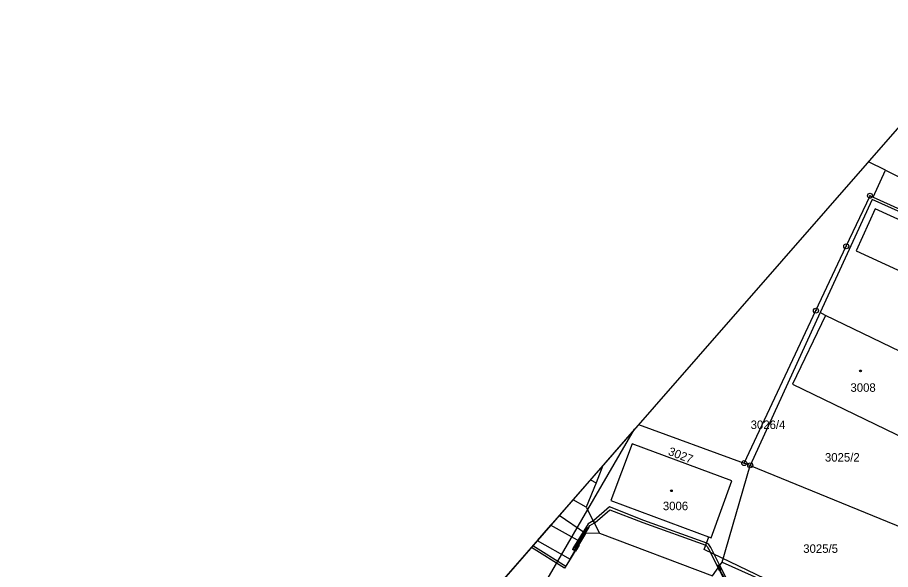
# Model space of a CAD drawing. Extents: x -620475 to -619963, y -1123010 to -1122510.
# Drawn here: x -620474.6 to -620299.9, y -1122620.5 to -1122510.1 of the extents above; entities that cross this region are included whole.
import ezdxf

# ---------------------------------------------------------------- set-up
doc = ezdxf.new("R2010")
doc.units = 0
for name, color, linetype in [('EON-podzemní NN', 7, 'Continuous'), ('HranDP', 7, 'Continuous'), ('Hranice parcel', 7, 'Continuous'), ('Parcelní čísla', 7, 'Continuous'), ('Rámečky', 7, 'Continuous'), ('Rámečky-tisk', 7, 'Continuous'), ('VAS vodovod', 7, 'Continuous'), ('Vnitřní kresba', 7, 'Continuous'), ('Vrstva 17', 7, 'Continuous'), ('Vrstva 9', 7, 'Continuous'), ('Věcná břemena k části', 7, 'Continuous'), ('Značky bodu BP', 7, 'Continuous'), ('Značky budov', 7, 'Continuous')]:
    doc.layers.add(name, color=color, linetype=linetype)

# ---------------------------------------------------------------- blocks, each defined once
blk = doc.blocks.new('NN630')
at = {"layer": 'Vrstva 9'}
for points in [[(0, -0.7), (-0.7, 0)], [(-0.7, -0.7), (-0.7, 0), (0.7, 0), (0.7, -0.7)], [(-0.7, -0.7), (0.7, -0.7)], [(0, -0.7), (0.7, 0)]]:
    blk.add_lwpolyline(points, dxfattribs=at)

msp = doc.modelspace()

# ---------------------------------------------------------------- linework, layer by layer
at = {"layer": 'EON-podzemní NN'}
msp.add_lwpolyline([(-620360.3, -1122612.01), (-620362.69, -1122615.91), (-620362.46, -1122616.07), (-620362.68, -1122616.4), (-620363.23, -1122616.02), (-620360.88, -1122612.19)], close=True, dxfattribs=at)
for points in [[(-620360.59, -1122612.1), (-620362.96, -1122615.97), (-620362.57, -1122616.24)], [(-620334.14, -1122620.77), (-620334.63, -1122619.57), (-620334.27, -1122619.68), (-620334.11, -1122619.78), (-620333.78, -1122620.6)], [(-620300.69, -1122640.97), (-620301.3, -1122641.21), (-620302.14, -1122640.6), (-620304.66, -1122639.27), (-620309.25, -1122636.6), (-620312.29, -1122634.86), (-620318.07, -1122631.51), (-620322.97, -1122628.77), (-620331.18, -1122624.09), (-620332.6, -1122623.11), (-620333.96, -1122620.69), (-620334.38, -1122619.64)]]:
    msp.add_lwpolyline(points, dxfattribs=at)
at = {"layer": 'HranDP'}
msp.add_line((-620358.11, -1122613.18), (-620335.54, -1122621.75), dxfattribs=at)
msp.add_lwpolyline([(-620358.11, -1122613.18), (-620360.91, -1122613.28), (-620361.94, -1122614.97), (-620364.03, -1122618.38), (-620365.14, -1122620.19), (-620371.77, -1122616.05)], dxfattribs=at)
at = {"layer": 'Hranice parcel'}
for p, q in [((-620300.93, -1122540.63), (-620304.33, -1122538.95)), ((-620303.36, -1122546.01), (-620300.93, -1122540.63)), ((-620303.56, -1122546.46), (-620313.95, -1122569.11)), ((-620269.23, -1122562), (-620303.56, -1122546.46)), ((-620303.36, -1122546.01), (-620269.35, -1122561.48)), ((-620313.95, -1122569.11), (-620327.97, -1122599.65)), ((-620312.88, -1122569.65), (-620313.95, -1122569.11)), ((-620350.31, -1122591.51), (-620329.18, -1122599.21)), ((-620357.46, -1122599.69), (-620358.78, -1122603.15)), ((-620333.59, -1122619.01), (-620327.97, -1122599.65)), ((-620327.97, -1122599.65), (-620329.18, -1122599.21)), ((-620327.97, -1122599.65), (-620295.2, -1122613.12)), ((-620358.78, -1122603.15), (-620360.83, -1122608.03)), ((-620359.97, -1122602.56), (-620358.78, -1122603.15)), ((-620360.83, -1122608.03), (-620363.43, -1122606.52)), ((-620360.83, -1122608.03), (-620358.11, -1122613.18)), ((-620358.11, -1122613.18), (-620335.54, -1122621.75)), ((-620335.54, -1122621.75), (-620333.59, -1122619.01))]:
    msp.add_line(p, q, dxfattribs=at)
for points in [[(-620300.93, -1122540.63), (-620280.94, -1122550.46), (-620278.42, -1122551.7)], [(-620329.18, -1122599.21), (-620314.82, -1122568.71), (-620308.76, -1122555.84), (-620304, -1122545.72), (-620303.36, -1122546.01)], [(-620306.78, -1122556.75), (-620268.73, -1122574.18), (-620264.84, -1122565.74), (-620303, -1122548.37), (-620306.78, -1122556.75)], [(-620312.88, -1122569.65), (-620319.52, -1122583.38), (-620298.85, -1122593.38), (-620295.91, -1122594.79), (-620292.71, -1122588.19)], [(-620292.71, -1122588.19), (-620289.27, -1122581.08), (-620292.27, -1122579.64), (-620312.88, -1122569.65)], [(-620335.8, -1122614.14), (-620331.64, -1122602.77), (-620351.59, -1122595.35), (-620355.84, -1122606.66), (-620335.8, -1122614.14)], [(-620358.11, -1122613.18), (-620360.91, -1122613.28), (-620361.94, -1122614.97), (-620364.03, -1122618.38), (-620365.14, -1122620.19), (-620371.77, -1122616.05)], [(-620333.59, -1122619.01), (-620307.23, -1122630.79), (-620302.25, -1122634.43)]]:
    msp.add_lwpolyline(points, dxfattribs=at)
at = {"layer": 'Rámečky'}
msp.add_lwpolyline([(-620279.07, -1122510.07), (-620474.61, -1122733.62), (-620158.49, -1123010.14)], dxfattribs=at)
at = {"layer": 'Rámečky-tisk'}
msp.add_line((-620351.12, -1122592.44), (-620471.94, -1122730.56), dxfattribs=at)
for points in [[(-620279.07, -1122510.07), (-620474.61, -1122733.62), (-620158.49, -1123010.14)], [(-620471.94, -1122730.56), (-620441.66, -1122748.16), (-620351.12, -1122592.44)]]:
    msp.add_lwpolyline(points, dxfattribs=at)
at = {"layer": 'VAS vodovod'}
msp.add_lwpolyline([(-620286.62, -1122632.6), (-620287.08, -1122632.39), (-620297.74, -1122627.56), (-620305.96, -1122631.45), (-620337.21, -1122616.49), (-620336.27, -1122613.97)], dxfattribs=at)
at = {"layer": 'Vnitřní kresba'}
msp.add_line((-620360.91, -1122613.28), (-620366.2, -1122609.68), dxfattribs=at)
at = {"layer": 'Vrstva 17'}
msp.add_line((-620364.89, -1122619.88), (-620371.5, -1122615.73), dxfattribs=at)
at = {"layer": 'Věcná břemena k části'}
msp.add_line((-620367.91, -1122611.63), (-620370.6, -1122614.71), dxfattribs=at)
for points in [[(-620332.41, -1122622.94), (-620334.05, -1122619.66), (-620335.86, -1122616.06), (-620336.23, -1122615.51), (-620336.65, -1122615.18), (-620349.27, -1122610.65), (-620356.14, -1122607.95), (-620359.28, -1122610.65), (-620359.41, -1122610.73), (-620359.17, -1122611.17), (-620358.98, -1122611.05), (-620356.04, -1122608.53), (-620349.45, -1122611.11), (-620336.89, -1122615.62), (-620336.61, -1122615.85), (-620336.3, -1122616.32), (-620334.39, -1122620.13), (-620332.8, -1122623.28)], [(-620370.6, -1122614.71), (-620364.03, -1122618.38), (-620362.52, -1122615.91), (-620361.94, -1122614.97), (-620367.91, -1122611.63)]]:
    msp.add_lwpolyline(points, dxfattribs=at)
msp.add_lwpolyline([(-620362.93, -1122616.59), (-620362.41, -1122615.74), (-620362.5, -1122615.69), (-620360.06, -1122611.71), (-620359.17, -1122611.17), (-620359.41, -1122610.73), (-620360.42, -1122611.35), (-620363.45, -1122616.28)], close=True, dxfattribs=at)
at = {"layer": 'Značky bodu BP'}
for centre, radius in [((-620304, -1122545.72), 0.5), ((-620304, -1122545.72), 0.0303), ((-620308.76, -1122555.84), 0.5), ((-620308.76, -1122555.84), 0.0303), ((-620314.82, -1122568.71), 0.5), ((-620314.82, -1122568.71), 0.0303), ((-620329.18, -1122599.21), 0.5), ((-620329.18, -1122599.21), 0.0303), ((-620327.97, -1122599.65), 0.5), ((-620327.97, -1122599.65), 0.0303)]:
    msp.add_circle(centre, radius, dxfattribs=at)
at = {"layer": 'Značky budov'}
for centre in [(-620305.9, -1122580.76), (-620343.74, -1122604.73)]:
    msp.add_circle(centre, 0.175, dxfattribs=at)

# ---------------------------------------------------------------- block references
at = {"layer": 'EON-podzemní NN', "rotation": -121.26648409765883}
msp.add_blockref('NN630', (-620362.57, -1122616.24), dxfattribs=at)

# ---------------------------------------------------------------- texts
at = {"layer": 'Parcelní čísla'}
for s, p in [('3008', (-620307.92, -1122584.94)), ('3026/4', (-620327.89, -1122592.38)), ('3025/2', (-620313.02, -1122598.9)), ('3006', (-620345.46, -1122608.62)), ('3025/5', (-620317.36, -1122617.15))]:
    msp.add_text(s, height=1.7, dxfattribs=at).set_placement(p)
msp.add_text('3027', height=1.7, rotation=339, dxfattribs=at).set_placement((-620344.54, -1122597.51))

doc.saveas('drawing.dxf')
